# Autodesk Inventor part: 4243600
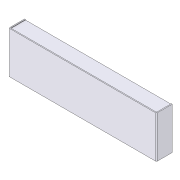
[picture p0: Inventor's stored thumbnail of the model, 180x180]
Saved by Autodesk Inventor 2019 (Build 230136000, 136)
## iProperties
Created: 2020-12
Part Number: 4243600
Material: Generic
Document SubType Name: Modeling
Designer: user
Density: 1 g/cm^3
Appearance: Default
Author: user
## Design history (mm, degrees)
node "Sketch1"
sketch "Sketch2"
  geometry: L1 (-150, 0)-(150, 0); L2 (150, 0)-(150, 32); L3 (150, 32)-(-150, 32); L4 (-150, 32)-(-150, 0); L5 (-148, 0)-(148, 0); L6 (148, 0)-(148, 30); L7 (148, 30)-(-148, 30); L8 (-148, 30)-(-148, 0); L9 (0, 0)-(0, 2.316); 1 further point
  constraints: 18 end point, 4 parallel, 2 perpendicular, 1 point on line, 2 other
  dimensions: "d2" = 2 distance between parallel lines of L8 L4; "d3" = 32 distance of L3.end L1.start; "d4" = 300 distance of L1.start L1.end; "d5" = 2 distance between parallel lines of L3 L7
extrude "Extrusion1" new body sketch "Sketch2" distance "d6" = 85; taper "d7" = 0 deg
workplane "Work Plane1"
sketch "Sketch3"
  geometry: L1 (148, 0)-(148, -30) reference; L2 (-148, -30)-(-148, 0) reference; L3 (148, 0)-(-148, 0); L4 (-148, 0)-(-148, -30); L5 (-148, -30)-(148, -30); L6 (148, -30)-(148, 0); 1 further point
  constraints: 8 end point, 2 parallel, 1 horizontal, 1 perpendicular
extrude "Extrusion2" new body sketch "Sketch3" distance "d9" = 83; taper "d10" = 0 deg
sketch "Sketch4"
  geometry: L1 (15, 71.85)-(15, 17.05); A1 r 2 centre (15, 69.85) between (15, 71.85) and (15, 67.85); A2 r 2 centre (15, 19.05) between (15, 21.05) and (15, 17.05); 1 further point
  constraints: 4 point on circle, 2 centre point, 2 end point, 2 point on line, 1 vertical
  dimensions: "d11" = 4 diameter of A1; "d12" = 4 diameter of A2
revolve "Revolution1" sketch "Sketch4" stored, may be unused: angle "d13" = 180 deg
workplane "Work Plane2"
sketch "Sketch5"
  geometry: L1 (0.56, -0.004)-(-0.004, -0.56); L2 (-0.004, -0.56)-(-0.56, 0.004); L3 (-0.56, 0.004)-(0.004, 0.56); L4 (0.004, 0.56)-(0.56, -0.004); L5 (50.8, -0.798)-(49.991, -0.018); L6 (49.991, -0.018)-(50.771, 0.79); L7 (50.771, 0.79)-(51.58, 0.01); L8 (51.58, 0.01)-(50.8, -0.798); 3 further points
  constraints: 16 end point, 18 other
extrude "Extrusion3" new body sketch "Sketch5" distance "d14" = 1; taper "d15" = 0 deg
fillet "Fillet1" dims "d16" = 2
body "Solid1"
body "Solid2"
body "Solid3"
body "Solid4"
other parameters: "d8" = -1
